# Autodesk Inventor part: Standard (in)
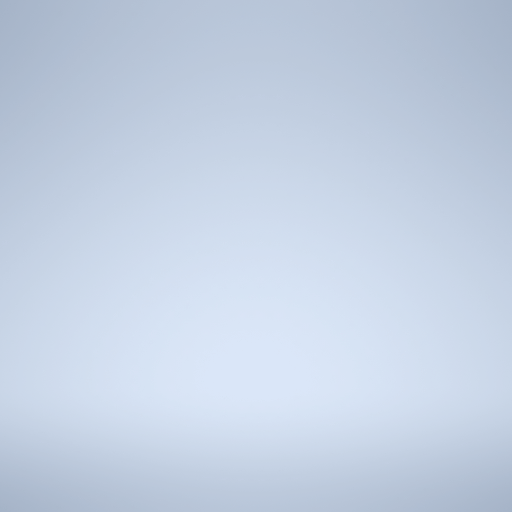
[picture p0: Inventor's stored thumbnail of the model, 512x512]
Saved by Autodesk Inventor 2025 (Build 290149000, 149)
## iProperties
Shininess: 64.0
Length Units: 11272
Angle Units: 11279
Time Units: 11290
Mass Units: 11286
Length Display Precision: 3
Angle Display Precision: 2
Compacted: True
Part Number: Standard (in)
Document SubType Name: Modeling
Created: 2002-08
Density: 1 g/cm^3
Material: Všeobecné
Appearance: Výchozí
Density: 0.0
Volumn: 0.0
Area: 0.0
PropertySet Name: Model Information
Control State: 0
Master: False
Checked Out: False
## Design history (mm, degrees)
